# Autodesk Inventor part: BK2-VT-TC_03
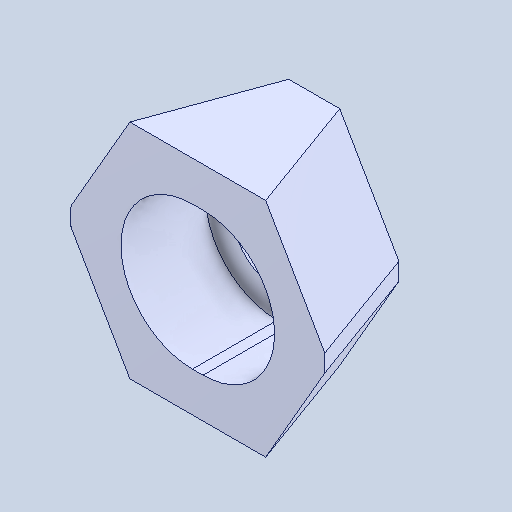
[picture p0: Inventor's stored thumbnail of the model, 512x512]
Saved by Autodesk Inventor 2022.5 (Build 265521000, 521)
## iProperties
Created: 2024-05
Part Number: BK2-VT-TC_03
Material: 一般
Document SubType Name: Modeling
Designer: ImaoCorp
Density: 1 g/cm^3
Appearance: 既定
Author: ImaoCorp
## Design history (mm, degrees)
feature "BK2-VT-TC_03"
node "ソリッド1"
